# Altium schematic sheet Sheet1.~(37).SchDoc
size A3
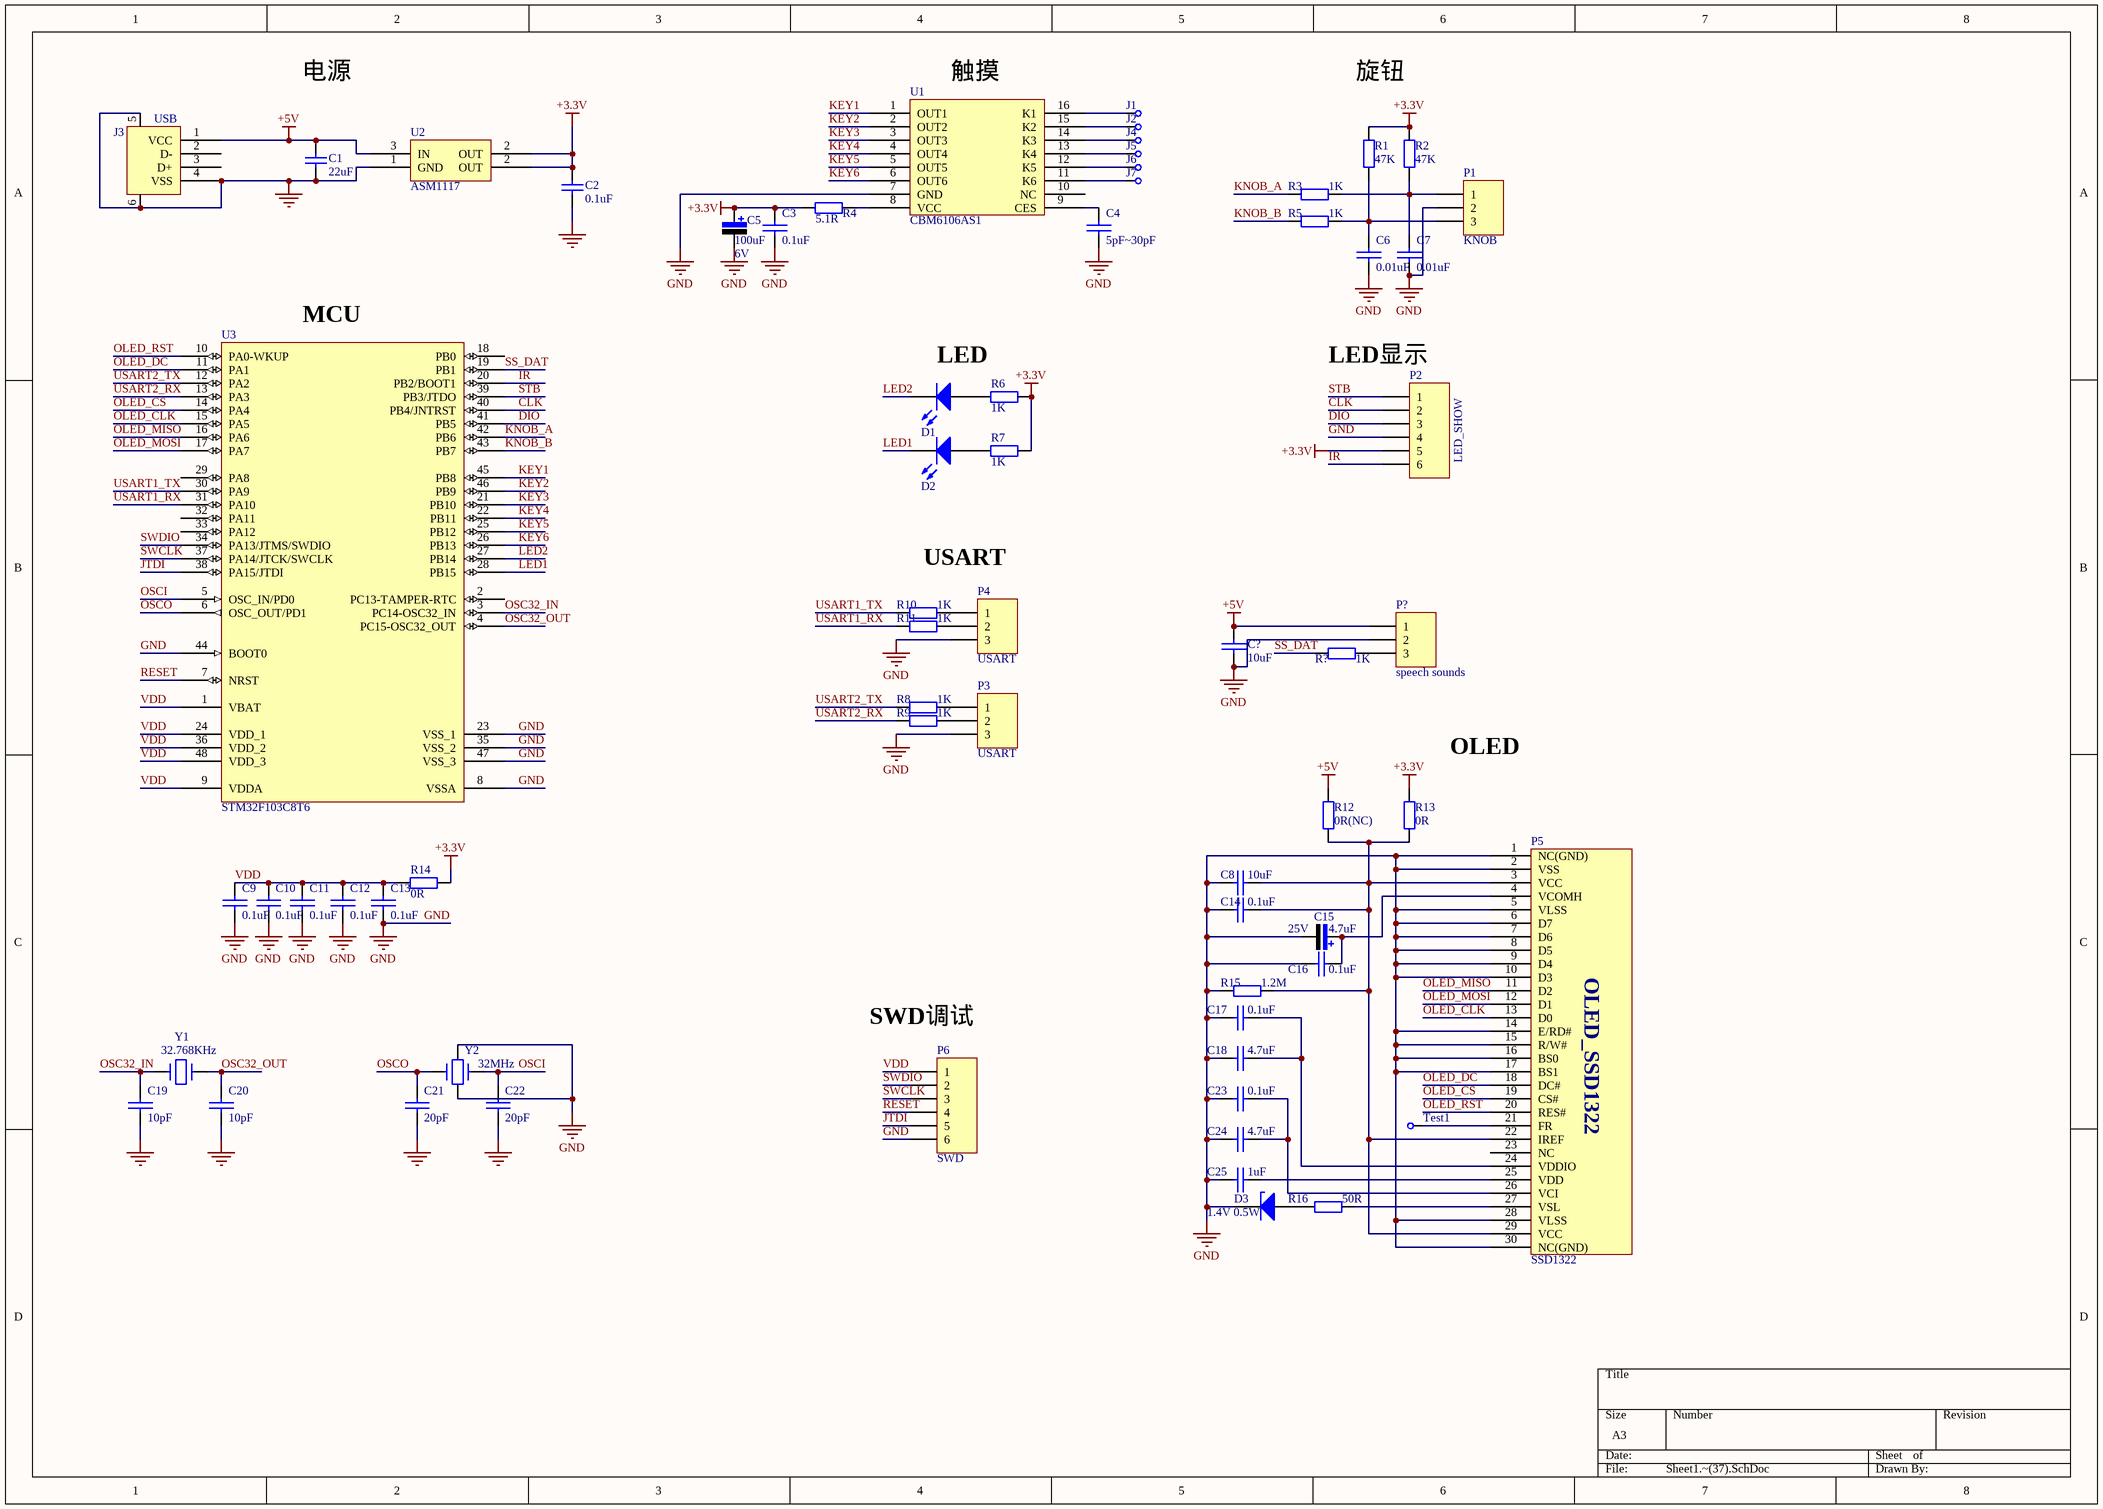
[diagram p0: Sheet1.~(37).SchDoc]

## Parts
C1  value 22uF  [0402C]  (hidden comment: Cap)
C2  value 0.1uF  [0402C]  (hidden comment: Cap)
C3  0.1uF  [0402C]
C4  5pF~30pF  [0402C]
C5  value 100uF  Vol: 6V  [CAP-3528]  (hidden comment: Cap Pol)
C6  0.01uF  [0402C]
C7  0.01uF  [0402C]
C8  10uF  [0402C]
C9  0.1uF  [0402C]
C10  0.1uF  [0402C]
C11  0.1uF  [0402C]
C12  0.1uF  [0402C]
C13  0.1uF  [0402C]
C14  0.1uF  [0402C]
C15  value 4.7uF  Vol: 25V  [CAP-3528]  (hidden comment: Cap Pol)
C16  0.1uF  [0402C]
C17  0.1uF  [0402C]
C18  4.7uF  [0402C]
C19  10pF  [0402C]
C20  10pF  [0402C]
C21  20pF  [0402C]
C22  20pF  [0402C]
C23  0.1uF  [0402C]
C24  4.7uF  [0402C]
C25  1uF  [0402C]
C?  10uF  [0402C]
D1  LED0  [led0603]  (value not drawn)
D2  LED0  [led0603]  (value not drawn)
D3  value 1.4V 0.5W  [DIODE-1206]  (hidden comment: Diode-Z)
J1  CHECK  [CHECK-A]  (value not drawn)
J2  CHECK  [CHECK-A]  (value not drawn)
J3  USB  [USB_A1]
J4  CHECK  [CHECK-A]  (value not drawn)
J5  CHECK  [CHECK-A]  (value not drawn)
J6  CHECK  [CHECK-A]  (value not drawn)
J7  CHECK  [CHECK-A]  (value not drawn)
P1  KNOB  [HDR3X1_A]
P2  LED_SHOW  [HDR6X1_B2]
P3  USART  [HDR3X1_A]
P4  USART  [HDR3X1_A]
P5  SSD1322
P6  SWD  [HDR6X1_B2]
P?  speech sounds  [HDR3X1_A]
R1  value 47K  [0603-1]  (hidden comment: Res1)
R2  value 47K  [0603-1]  (hidden comment: Res1)
R3  value 1K  [0603-1]  (hidden comment: Res1)
R4  value 5.1R  [0603-1]  (hidden comment: Res1)
R5  value 1K  [0603-1]  (hidden comment: Res1)
R6  value 1K  [0402R]  (hidden comment: Res1)
R7  value 1K  [0402R]  (hidden comment: Res1)
R8  value 1K  [0402R]  (hidden comment: Res1)
R9  value 1K  [0402R]  (hidden comment: Res1)
R10  value 1K  [0402R]  (hidden comment: Res1)
R11  value 1K  [0402R]  (hidden comment: Res1)
R12  value 0R(NC)  [0402R]  (hidden comment: Res1)
R13  value 0R  [0402R]  (hidden comment: Res1)
R14  value 0R  [0402R]  (hidden comment: Res1)
R15  value 1.2M  [0402R]  (hidden comment: Res1)
R16  value 50R  [0402R]  (hidden comment: Res1)
R?  value 1K  [0402R]  (hidden comment: Res1)
Test1  CHECK  [CHECK-A]  (value not drawn)
U1  CBM6106AS1
U2  ASM1117  [SOT-223-3]
U3  STM32F103C8T6  [LQFP48_N]
Y1  32.768KHz  [SMD3215]
Y2  32MHz  [Y3225]

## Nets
+3.3V: C2.2 C3.1 C5.1 P2.5 R1.2 R2.2 R4.1 R6.1 R7.1 R13.1 R14.2 U2.2(OUT)
+5V: C1.2 C?.1 J3.1(VCC) P?.1 R12.1 U2.3(IN)
GND: C1.1 C2.1 C3.2 C4.2 C5.2 C6.2 C7.2 C8.2 C9.2 C10.2 C11.2 C12.2 C13.2 C14.2 C15.2 C16.2 C17.2 C18.2 C19.2 C20.2 C21.2 C22.2 C23.2 C24.2 C25.2 C?.2 D3.2(K) J3.4(VSS) J3.5 J3.6 P1.2 P2.4 P3.3 P4.3 P5.1(NC(GND)) P5.2(VSS) P5.5(VLSS) P5.6(D7) P5.7(D6) P5.8(D5) P5.9(D4) P5.10(D3) P5.14(E/RD#) P5.15(R/W#) P5.16(BS0) P5.17(BS1) P5.28(VLSS) P5.30(NC(GND)) P6.6 P?.2 R15.2 U1.7(GND) U2.1(GND) U3.8(VSSA) U3.23(VSS_1) U3.35(VSS_2) U3.44(BOOT0) U3.47(VSS_3) Y2.2 Y2.4
CLK: P2.2 U3.40(PB4/JNTRST)
DIO: P2.3 U3.41(PB5)
IR: P2.6 U3.20(PB2/BOOT1)
JTDI: P6.5 U3.38(PA15/JTDI)
KEY1: U1.1(OUT1) U3.45(PB8)
KEY2: U1.2(OUT2) U3.46(PB9)
KEY3: U1.3(OUT3) U3.21(PB10)
KEY4: U1.4(OUT4) U3.22(PB11)
KEY5: U1.5(OUT5) U3.25(PB12)
KEY6: U1.6(OUT6) U3.26(PB13)
KNOB_A: R3.1 U3.42(PB6)
KNOB_B: R5.1 U3.43(PB7)
LED1: D2.2(K) U3.28(PB15)
LED2: D1.2(K) U3.27(PB14)
OLED_CLK: P5.13(D0) U3.15(PA5)
OLED_CS: P5.19(CS#) U3.14(PA4)
OLED_DC: P5.18(DC#) U3.11(PA1)
OLED_MISO: P5.11(D2) U3.16(PA6)
OLED_MOSI: P5.12(D1) U3.17(PA7)
OLED_RST: P5.20(RES#) U3.10(PA0-WKUP)
OSC32_IN: C19.1 U3.3(PC14-OSC32_IN) Y1.1
OSC32_OUT: C20.1 U3.4(PC15-OSC32_OUT) Y1.2
OSCI: C22.1 U3.5(OSC_IN/PD0) Y2.3
OSCO: C21.1 U3.6(OSC_OUT/PD1) Y2.1
RESET: P6.4 U3.7(NRST)
SS_DAT: R?.2 U3.19(PB1)
STB: P2.1 U3.39(PB3/JTDO)
SWCLK: P6.3 U3.37(PA14/JTCK/SWCLK)
SWDIO: P6.2 U3.34(PA13/JTMS/SWDIO)
USART1_RX: R11.2 U3.31(PA10)
USART1_TX: R10.2 U3.30(PA9)
USART2_RX: R9.2 U3.13(PA3)
USART2_TX: R8.2 U3.12(PA2)
VDD: C9.1 C10.1 C11.1 C12.1 C13.1 P6.1 R14.1 U3.1(VBAT) U3.9(VDDA) U3.24(VDD_1) U3.36(VDD_2) U3.48(VDD_3)
NetC4_1: C4.1 U1.9(CES)
NetC6_1: C6.1 P1.3 R1.1 R5.2
NetC7_1: C7.1 P1.1 R2.1 R3.2
NetC8_1: C8.1 C14.1 P5.3(VCC) P5.22(IREF) P5.29(VCC) R12.2 R13.2 R15.1
NetC15_1: C15.1 C16.1 P5.4(VCOMH)
NetC17_1: C17.1 C18.1 P5.24(VDDIO)
NetC23_1: C23.1 C24.1 P5.26(VCI)
NetC25_1: C25.1 P5.25(VDD)
NetD1_1: D1.1(A) R6.2
NetD2_1: D2.1(A) R7.2
NetD3_1: D3.1(A) R16.2
NetJ1_1: J1.1 U1.16(K1)
NetJ2_1: J2.1 U1.15(K2)
NetJ4_1: J4.1 U1.14(K3)
NetJ5_1: J5.1 U1.13(K4)
NetJ6_1: J6.1 U1.12(K5)
NetJ7_1: J7.1 U1.11(K6)
NetP3_1: P3.1 R8.1
NetP3_2: P3.2 R9.1
NetP4_1: P4.1 R10.1
NetP4_2: P4.2 R11.1
NetP5_21: P5.21(FR) Test1.1
NetP5_27: P5.27(VSL) R16.1
NetP?_3: P?.3 R?.1
NetR4_2: R4.2 U1.8(VCC)

Not connected (* = marked no-connect by the designer): J3 2(D-) 3(D+); P5 23(NC); U1 10(NC); U3 2(PC13-TAMPER-RTC) 18(PB0) 29(PA8) 32(PA11) 33(PA12)

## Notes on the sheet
- 电源
- (near U1) 触摸
- 旋钮
- (near U3) MCU
- LED
- (near P2) LED显示
- USART
- OLED
- (near P6) SWD调试

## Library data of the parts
C1 C2 = Cap: 无极性电容
C3 C4 C6-C14 C16-C25 C? = CAP: Capacitor
C5 C15 = Cap Pol: 极性电解电容
D1 D2 = LED0: 发光二极管
D3 = Diode-Z: 稳压二极管
J1 J2 J4-J7 Test1 = CHECK: 测试点
J3 = USB: USB接口
P1 P3 P4 P? = Header 3: 接插件
P2 P6 = Header 6: 接插件
R1-R16 R? = Res1: 贴片电阻
U2 = ASM1117: 3.3V稳压芯片
U3 = STM32F103C8T6: STM32 ARM-based 32-bit MCU with 64 Kbytes Flash, 48-pin LQFP, Industrial Temperature
Y1 = CRYSTAL
Y2 = CRYSTAL1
